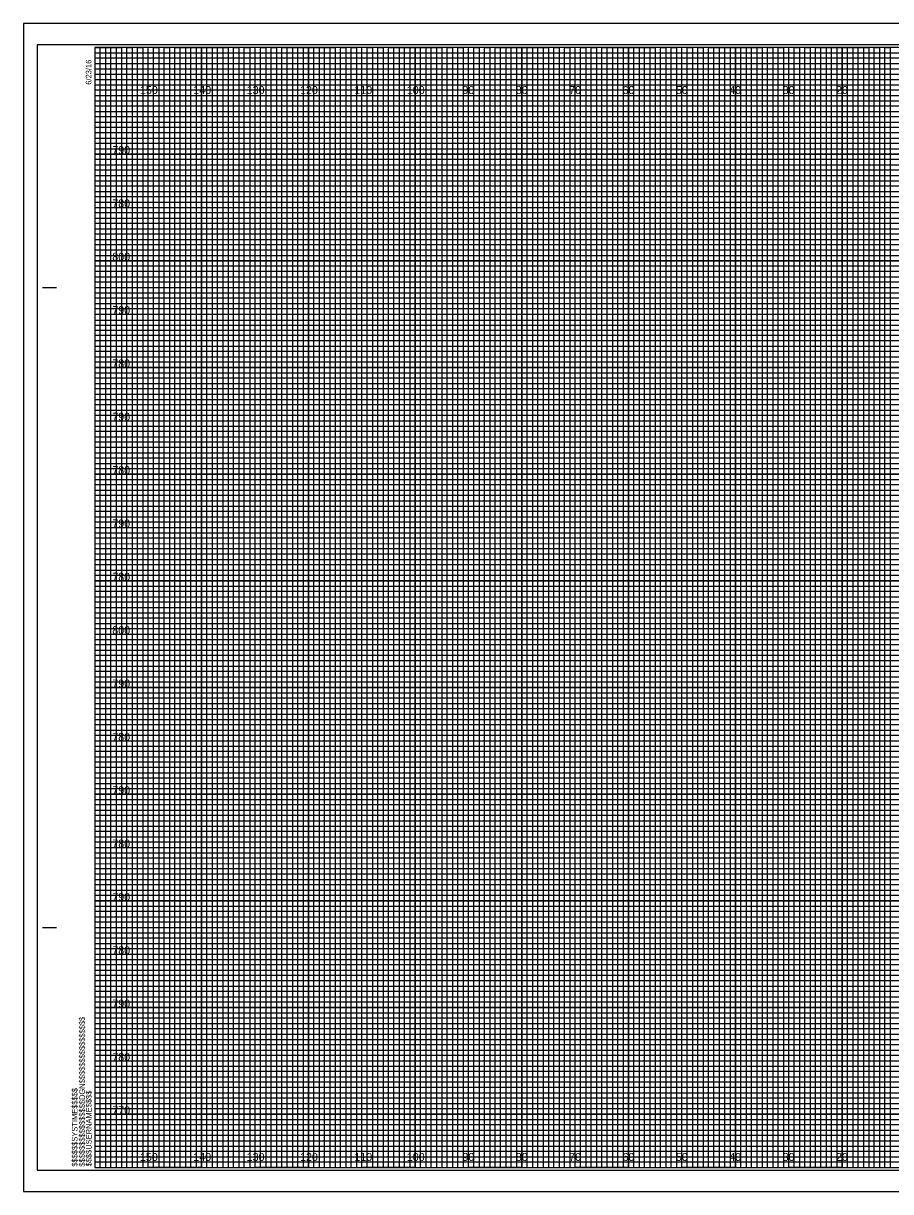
# Model space of a CAD drawing. Extents: x -13 to 323, y -5 to 215.
# Drawn here: x -13.4 to 149.1, y -4.5 to 214.5 of the extents above; entities that cross this region are included whole.
import ezdxf

# ---------------------------------------------------------------- set-up
doc = ezdxf.new("R2010")
doc.units = 0
for name, color, linetype in [('Prop XS Label Text', 7, 'Continuous'), ('Prop XS Offset Labels', 7, 'Continuous'), ('Prop XS Side Slope Text', 7, 'Continuous'), ('Sheet Cross Section Grid Major CELL', 7, 'Continuous'), ('Sheet Cross Section Grid Middle CELL', 7, 'Continuous'), ('Sheet Cross Section Grid Minor 1 CELL', 7, 'Continuous'), ('Sheet Cross Section Grid Minor 2 CELL', 7, 'Continuous'), ('Sheet Cross Section Scale CELL', 7, 'Continuous'), ('Sheet DOT Grid CELL', 7, 'Continuous'), ('Sheet Plot Border Inside CELL', 7, 'Continuous'), ('Sheet Plot Border Outside CELL', 7, 'Continuous')]:
    doc.layers.add(name, color=color, linetype=linetype)

msp = doc.modelspace()

# ---------------------------------------------------------------- linework, layer by layer
at = {"layer": 'Prop XS Label Text'}
for p, q in [((10, 210), (0, 210)), ((10, 0), (10, 210)), ((30, 210), (20, 210)), ((20, 210), (20, 0)), ((30, 0), (30, 210)), ((50, 210), (40, 210)), ((40, 210), (40, 0)), ((50, 0), (50, 210)), ((70, 210), (60, 210)), ((60, 210), (60, 0)), ((70, 0), (70, 210)), ((90, 210), (80, 210)), ((80, 210), (80, 0)), ((90, 0), (90, 210)), ((110, 210), (100, 210)), ((100, 210), (100, 0)), ((110, 0), (110, 210)), ((130, 210), (120, 210)), ((120, 210), (120, 0)), ((130, 0), (130, 210)), ((150, 210), (140, 210)), ((140, 210), (140, 0)), ((20, 0), (10, 0)), ((40, 0), (30, 0)), ((60, 0), (50, 0)), ((80, 0), (70, 0)), ((100, 0), (90, 0)), ((120, 0), (110, 0)), ((140, 0), (130, 0))]:
    msp.add_line(p, q, dxfattribs=at)
for points in [[(0, 200), (320, 200), (320, 190), (0, 190)], [(0, 180), (320, 180), (320, 170), (0, 170)], [(0, 160), (320, 160), (320, 150), (0, 150)], [(0, 140), (320, 140), (320, 130), (0, 130)], [(0, 120), (320, 120), (320, 110), (0, 110)], [(0, 100), (320, 100), (320, 90), (0, 90)], [(0, 80), (320, 80), (320, 70), (0, 70)], [(0, 60), (320, 60), (320, 50), (0, 50)], [(0, 40), (320, 40), (320, 30), (0, 30)], [(0, 20), (320, 20), (320, 10), (0, 10)]]:
    msp.add_lwpolyline(points, dxfattribs=at)
at = {"layer": 'Prop XS Offset Labels'}
for points in [[(0, 210), (5, 210), (5, 0), (15, 0), (15, 210), (25, 210), (25, 0), (35, 0), (35, 210), (45, 210), (45, 0), (55, 0), (55, 210), (65, 210), (65, 0), (75, 0), (75, 210), (85, 210), (85, 0), (95, 0), (95, 210), (105, 210), (105, 0), (115, 0), (115, 210), (125, 210), (125, 0), (135, 0), (135, 210), (145, 210), (145, 0), (155, 0)], [(0, 205), (275, 205)], [(0, 185), (320, 185), (320, 195), (0, 195)], [(0, 165), (320, 165), (320, 175), (0, 175)], [(0, 145), (320, 145), (320, 155), (0, 155)], [(0, 125), (320, 125), (320, 135), (0, 135)], [(0, 105), (320, 105), (320, 115), (0, 115)], [(0, 85), (320, 85), (320, 95), (0, 95)], [(0, 65), (320, 65), (320, 75), (0, 75)], [(0, 45), (320, 45), (320, 55), (0, 55)], [(0, 25), (320, 25), (320, 35), (0, 35)], [(0, 5), (320, 5), (320, 15), (0, 15)]]:
    msp.add_lwpolyline(points, dxfattribs=at)
at = {"layer": 'Sheet Cross Section Grid Major CELL'}
for p, q in [((0, 209), (260, 209)), ((260, 207.98), (0, 207.98)), ((0, 207.98), (0, 207)), ((0, 207), (260, 207)), ((260, 205.89), (0, 205.89)), ((0, 205.89), (0, 204)), ((0, 204), (320, 204))]:
    msp.add_line(p, q, dxfattribs=at)
for points in [[(0, 203), (270, 203), (320, 203), (320, 202), (0, 202)], [(0, 201), (320, 201), (320, 199), (0, 199)], [(0, 198), (320, 198), (320, 197), (0, 196.98)], [(0, 196), (320, 196), (320, 194), (0, 194)], [(0, 193), (320, 193), (320, 192), (0, 192)], [(0, 191), (320, 191), (320, 189), (0, 189)], [(0, 188), (320, 188), (320, 187), (0, 187)], [(0, 186), (320, 186), (320, 184), (0, 184)], [(0, 183), (320, 183), (320, 182), (0, 182)], [(0, 181), (320, 181), (320, 179), (0, 179)], [(0, 178), (320, 178), (320, 177), (0, 177)], [(0, 176), (320, 176), (320, 173.95), (320, 173), (320, 172), (0, 172)], [(0, 174), (320, 174), (320, 173), (0, 173)], [(0, 171), (320, 171), (320, 169), (0, 169.03)], [(0, 169.03), (320, 169), (320, 168), (0, 168)], [(0, 167), (320, 167), (320, 166), (0, 166)], [(0, 164), (320, 164), (320, 163), (0, 163)], [(0, 162), (320, 162), (320, 161), (0, 161)], [(-0.07, 158.89), (320, 158.89), (320, 157.88), (-0.07, 157.88)], [(0, 157), (320, 157), (320, 156), (0, 156)], [(0, 154), (320, 154), (320, 153), (0, 153)], [(0, 152), (320, 152), (320, 151), (0, 151)], [(0, 149), (320, 149), (320, 148), (0, 148)], [(0, 147), (320, 147), (320, 146), (0, 146)], [(0, 144), (320, 144), (320, 143), (0, 143)], [(0, 142), (320, 142), (320, 141), (0, 141)], [(0, 139), (320, 139), (319.99, 137.98), (0, 138)], [(0, 137), (320, 137), (320, 136), (0, 136)], [(0, 134), (320, 134), (320, 133), (0, 133)], [(0, 132), (320, 132), (320, 131), (0, 131)], [(0, 129), (320, 129), (320, 128), (0, 128)], [(0, 127), (320, 127), (320, 126), (0, 126)], [(0, 124), (320, 124), (320, 123), (0, 123)], [(0, 122), (320, 122), (320, 121), (0, 121)], [(0, 119), (320, 119), (320, 118), (0, 118)], [(0, 116.99), (320.07, 116.91), (320, 116), (0, 116)], [(0, 114), (320, 114), (320, 113), (0, 113)], [(0, 112), (320, 112), (320, 111), (0, 111)], [(0, 109), (320, 109), (320, 108), (0, 108)], [(0, 107), (320, 107), (320, 106), (0, 106)], [(0, 104), (320, 104), (320, 103), (0, 103)], [(0, 102), (320, 102), (320, 101), (0, 101)], [(0, 99), (320, 99), (320, 98), (0, 98)], [(0, 97), (320, 97), (320, 96), (0, 96)], [(0, 94), (320, 94), (320, 93), (0, 93)], [(0, 92), (320, 92), (320, 91), (0, 91)], [(0, 89), (320, 89), (320, 88), (0, 88)], [(0, 87), (320, 87), (320, 86), (0, 86)], [(0, 84), (320, 84), (320, 83), (0, 83)], [(0, 82), (320, 82), (320, 81), (0, 81)], [(0, 79), (320, 79), (319.99, 77.98), (0, 78)], [(0, 77), (320, 77), (320, 76), (0, 76)], [(0, 74), (320, 74), (320, 73), (0, 73)], [(0, 72), (320, 72), (320, 71), (0, 71)], [(0, 69), (320, 69), (320, 68), (0, 68)], [(0, 67), (320, 67), (320, 66), (0, 66)], [(0, 64), (320, 64), (320, 63), (0, 63)], [(0, 62), (320, 62), (320, 61), (0, 61)], [(0, 59), (320, 59), (320, 58), (0, 58)], [(0, 56.99), (320.07, 56.91), (320, 56), (0, 56)], [(0, 54), (320, 54), (320, 53), (0, 53)], [(0, 52), (320, 52), (320, 51), (0, 51)], [(0, 49), (320, 49), (320, 48), (0, 48)], [(0, 47), (320, 47), (320, 46), (0, 46)], [(0, 44), (320, 44), (320, 43), (0, 43)], [(0, 42), (320, 42), (320, 41), (0, 41)], [(0, 39), (320, 39), (320, 38), (0, 38)], [(0, 37), (320, 37), (320, 36), (0, 36)], [(0, 34), (320, 34), (320, 33), (0, 33)], [(0, 32), (320, 32), (320, 31), (0, 31)], [(0, 29), (320, 29), (320, 28), (0, 28)], [(0, 27), (320, 27), (320, 26), (0, 26)], [(0, 24), (320, 24), (320, 23), (0, 23)], [(0, 22), (320, 22), (320, 21), (0, 21)], [(0, 19), (320, 19), (320, 18), (0, 18)], [(0, 17), (320, 17), (320, 16), (0, 16)], [(0, 14), (320, 14), (320, 13), (0, 13)], [(0, 12), (320, 12), (320, 11), (0, 11)], [(0, 9), (320, 9), (320, 8), (0, 8)], [(0, 7), (320, 7), (320, 6), (0, 6)], [(0, 4), (320, 4), (320, 3), (0, 3)], [(0, 2), (320, 2), (320, 1), (0, 1)]]:
    msp.add_lwpolyline(points, dxfattribs=at)
at = {"layer": 'Sheet Cross Section Grid Middle CELL'}
for p, q in [((-9.8, 165), (-7.3, 165)), ((-9.7, 165), (-7.2, 165)), ((-9.8, 45), (-7.3, 45)), ((-9.7, 45), (-7.2, 45)), ((0, 0), (0, 0)), ((0, 0), (0, 0)), ((0, 0), (0, 0)), ((0, 0), (0, 0)), ((0, 0), (0, 0)), ((0, 0), (0, 0)), ((0, 0), (0, 0))]:
    msp.add_line(p, q, dxfattribs=at)
msp.add_lwpolyline([(320, 210), (0, 210), (0, 0), (320, 0)], close=True, dxfattribs=at)
at = {"layer": 'Sheet Cross Section Grid Minor 1 CELL'}
for points in [[(0, 0), (1, 0), (1, 210), (2, 210), (2, 0)], [(2, 0), (3, 0), (3, 210), (4, 210), (4, 0)], [(5, 0), (6, 0), (6, 210), (7, 210), (7, 0)], [(7, 0), (8, 0), (8, 210), (9, 210), (9, 0)], [(10, 0), (11, 0), (11, 210), (12, 210), (12, 0)], [(12, 0), (13, 0), (13, 210), (14, 210), (14, 0)], [(15, 0), (16, 0), (16, 210), (17, 210), (17, 0)], [(17, 0), (18, 0), (18, 210), (19, 210), (19, 0)], [(20, 0), (21, 0), (21, 210), (22, 210), (22, 0)], [(22, 0), (23, 0), (23, 210), (24, 210), (24, 0)], [(25, 0), (26, 0), (26, 210), (27, 210), (27, 0)], [(27, 0), (28, 0), (28, 210), (29, 210), (29, 0)], [(30, 0), (31, 0), (31, 210), (32, 210), (32, 0)], [(32, 0), (33, 0), (33, 210), (34, 210), (34, 0)], [(35, 0), (36, 0), (36, 210), (37, 210), (37, 0)], [(37, 0), (38, 0), (38, 210), (39, 210), (39, 0)], [(40, 0), (41, 0), (41, 210), (42, 210), (42, 0)], [(42, 0), (43, 0), (43, 210), (44, 210), (44, 0)], [(45, 0), (46, 0), (46, 210), (47, 210), (47, 0)], [(47, 0), (48, 0), (48, 210), (49, 210), (49, 0)], [(50, 0), (51, 0), (51, 210), (52, 210), (52, 0)], [(52, 0), (53, 0), (53, 210), (54, 210), (54, 0)], [(55, 0), (56, 0), (56, 210), (57, 210), (57, 0)], [(57, 0), (58, 0), (58, 210), (59, 210), (59, 0)], [(60, 0), (61, 0), (61, 210), (62, 210), (62, 0)], [(62, 0), (63, 0), (63, 210), (64, 210), (64, 0)], [(65, 0), (66, 0), (66, 210), (67, 210), (67, 0)], [(67, 0), (68, 0), (68, 210), (69, 210), (69, 0)], [(70, 0), (71, 0), (71, 210), (72, 210), (72, 0)], [(72, 0), (73, 0), (73, 210), (74, 210), (74, 0)], [(75, 0), (76, 0), (76, 210), (77, 210), (77, 0)], [(77, 0), (78, 0), (78, 210), (79, 210), (79, 0)], [(80, 0), (81, 0), (81, 210), (82, 210), (82, 0)], [(82, 0), (83, 0), (83, 210), (84, 210), (84, 0)], [(85, 0), (86, 0), (86, 210), (87, 210), (87, 0)], [(87, 0), (88, 0), (88, 210), (89, 210), (89, 0)], [(90, 0), (91, 0), (91, 210), (92, 210), (92, 0)], [(92, 0), (93, 0), (93, 210), (94, 210), (94, 0)], [(95, 0), (96, 0), (96, 210), (97, 210), (97, 0)], [(97, 0), (98, 0), (98, 210), (99, 210), (99, 0)], [(100, 0), (101, 0), (101, 210), (102, 210), (102, 0)], [(102, 0), (103, 0), (103, 210), (104, 210), (104, 0)], [(105, 0), (106, 0), (106, 210), (107, 210), (107, 0)], [(107, 0), (108, 0), (108, 210), (109, 210), (109, 0)], [(110, 0), (111, 0), (111, 210), (112, 210), (112, 0)], [(112, 0), (113, 0), (113, 210), (114, 210), (114, 0)], [(115, 0), (116, 0), (116, 210), (117, 210), (117, 0)], [(117, 0), (118, 0), (118, 210), (119, 210), (119, 0)], [(120, 0), (121, 0), (121, 210), (122, 210), (122, 0)], [(122, 0), (123, 0), (123, 210), (124, 210), (124, 0)], [(125, 0), (126, 0), (126, 210), (127, 210), (127, 0)], [(127, 0), (128, 0), (128, 210), (129, 210), (129, 0)], [(130, 0), (131, 0), (131, 210), (132, 210), (132, 0)], [(132, 0), (133, 0), (133, 210), (134, 210), (134, 0)], [(135, 0), (136, 0), (136, 210), (137, 210), (137, 0)], [(137, 0), (138, 0), (138, 210), (139, 210), (139, 0)], [(140, 0), (141, 0), (141, 210), (142, 210), (142, 0)], [(142, 0), (143, 0), (143, 210), (144, 210), (144, 0)], [(145, 0), (146, 0), (146, 210), (147, 210), (147, 0)], [(147, 0), (148, 0), (148, 210), (149, 210), (149, 0)]]:
    msp.add_lwpolyline(points, dxfattribs=at)
at = {"layer": 'Sheet Cross Section Grid Minor 2 CELL'}
msp.add_lwpolyline([(-13.4, -4.5), (323.3, -4.5), (323.3, 214.5), (-13.4, 214.5)], close=True, dxfattribs=at)
at = {"layer": 'Sheet Cross Section Scale CELL'}
msp.add_lwpolyline([(-10.8, -0.5), (322.4, -0.5), (322.4, 210.5), (-10.8, 210.5)], close=True, dxfattribs=at)
at = {"layer": 'Sheet Plot Border Inside CELL'}
for p, q in [((323.3, 214.5), (-13.4, 214.5)), ((-13.4, 214.5), (-13.4, -4.5)), ((-13.4, -4.5), (323.3, -4.5))]:
    msp.add_line(p, q, dxfattribs=at)
at = {"layer": 'Sheet Plot Border Outside CELL'}
for p, q in [((10, 0), (10, 210)), ((20, 0), (20, 210)), ((30, 0), (30, 210)), ((40, 0), (40, 210)), ((50, 0), (50, 210)), ((60, 0), (60, 210)), ((70, 0), (70, 210)), ((80, 0), (80, 210)), ((90, 0), (90, 210)), ((100, 0), (100, 210)), ((110, 0), (110, 210)), ((120, 0), (120, 210)), ((130, 0), (130, 210)), ((140, 0), (140, 210)), ((0, 200), (320, 200)), ((0, 190), (320, 190)), ((0, 180), (320, 180)), ((0, 170), (320, 170)), ((0, 160), (320, 160)), ((0, 150), (320, 150)), ((0, 140), (320, 140)), ((0, 130), (320, 130)), ((0, 120), (320, 120)), ((0, 110), (320, 110)), ((0, 100), (320, 100)), ((0, 90), (320, 90)), ((0, 80), (320, 80)), ((0, 70), (320, 70)), ((0, 60), (320, 60)), ((0, 50), (320, 50)), ((0, 40), (320, 40)), ((0, 30), (320, 30)), ((0, 20), (320, 20)), ((0, 10), (320, 10))]:
    msp.add_line(p, q, dxfattribs=at)

# ---------------------------------------------------------------- texts
at = {"layer": 'Prop XS Side Slope Text'}
for s, p in [('150', (8.44, 201.25)), ('140', (18.44, 201.25)), ('130', (28.44, 201.25)), ('120', (38.44, 201.25)), ('110', (48.62, 201.25)), ('100', (58.44, 201.25)), ('90', (68.86, 201.25)), ('80', (78.86, 201.25)), ('70', (88.86, 201.25)), ('60', (98.86, 201.25)), ('50', (108.86, 201.25)), ('40', (118.86, 201.25)), ('30', (128.86, 201.25)), ('20', (138.86, 201.25)), ('150', (8.44, 1.25)), ('140', (18.44, 1.25)), ('130', (28.44, 1.25)), ('120', (38.44, 1.25)), ('110', (48.62, 1.25)), ('100', (58.44, 1.25)), ('90', (68.86, 1.25)), ('80', (78.86, 1.25)), ('70', (88.86, 1.25)), ('60', (98.86, 1.25)), ('50', (108.86, 1.25)), ('40', (118.86, 1.25)), ('30', (128.86, 1.25)), ('20', (138.86, 1.25))]:
    msp.add_text(s, height=1.5, dxfattribs=at).set_placement(p)
at = {"layer": 'Sheet Cross Section Grid Middle CELL'}
for s, p in [('6/23/16', (-0.65, 203)), ('$$$$$$$$$$$$$$$$DGN$$$$$$$$$$$$$$$$', (-1.88, 0.18)), ('$$$$$$SYSTIME$$$$$', (-3.26, 0.18)), ('$$$$USERNAME$$$$', (-0.62, 0.23))]:
    msp.add_text(s, height=1.05, rotation=90, dxfattribs=at).set_placement(p)
at = {"layer": 'Sheet DOT Grid CELL'}
for s, p in [('790', (3.26, 190)), ('780', (3.26, 180)), ('800', (3.26, 170)), ('790', (3.26, 160)), ('780', (3.26, 150)), ('790', (3.26, 140)), ('780', (3.26, 130)), ('790', (3.26, 120)), ('780', (3.26, 110)), ('800', (3.26, 100)), ('790', (3.26, 90)), ('780', (3.26, 80)), ('790', (3.26, 70)), ('780', (3.26, 60)), ('790', (3.26, 50)), ('780', (3.26, 40)), ('790', (3.26, 30)), ('780', (3.26, 20)), ('770', (3.26, 10))]:
    msp.add_text(s, height=1.5, dxfattribs=at).set_placement(p)

doc.saveas('drawing.dxf')
